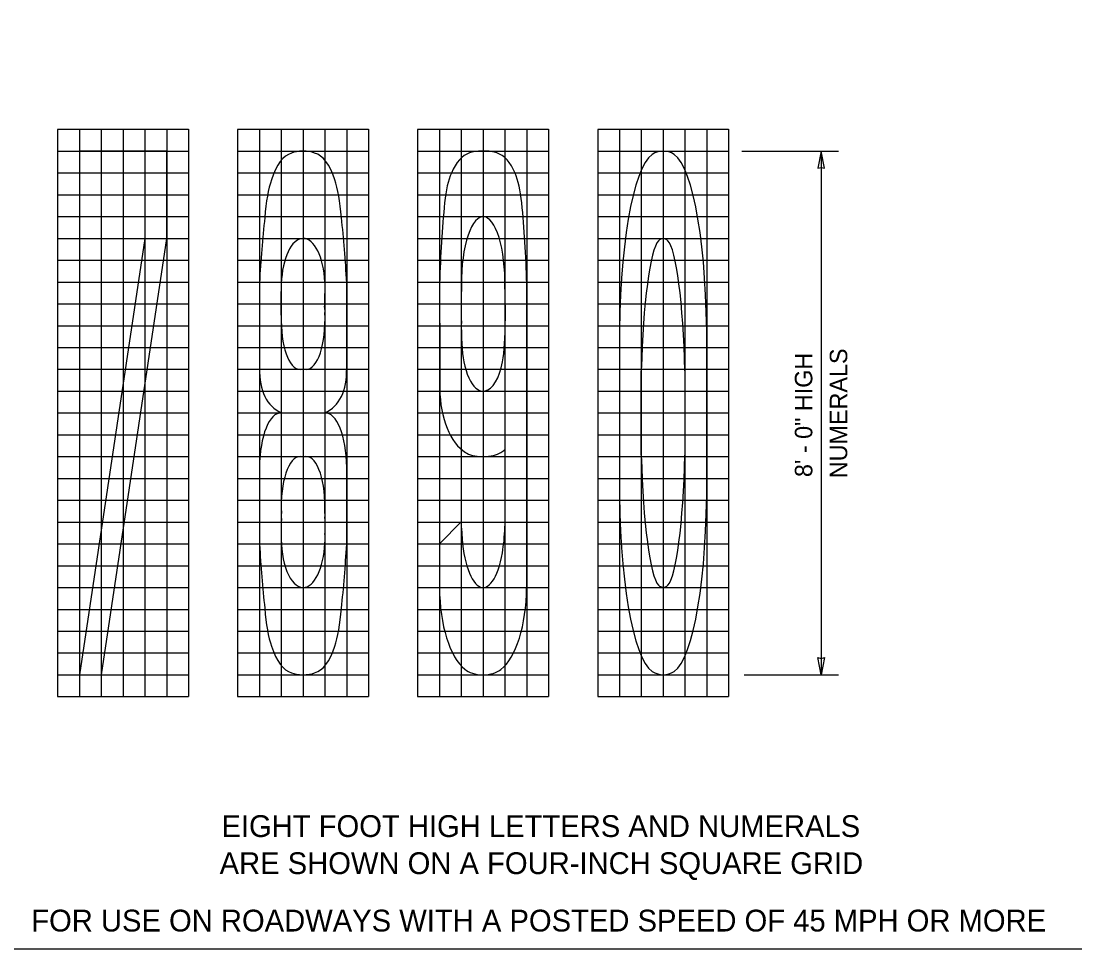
# Model space of a CAD drawing. Extents: x 99862 to 103151, y 100000 to 102076.
# Drawn here: x 100962 to 101927, y 100000 to 100850 of the extents above; entities that cross this region are included whole.
import ezdxf

# ---------------------------------------------------------------- set-up
doc = ezdxf.new("R2010")
doc.units = 0
for name, color, linetype in [('Level 1', 7, 'Continuous'), ('Level 15', 7, 'Continuous'), ('Level 20', 7, 'Continuous'), ('Level 4', 7, 'Continuous')]:
    doc.layers.add(name, color=color, linetype=linetype)

msp = doc.modelspace()

# ---------------------------------------------------------------- linework, layer by layer
at = {"layer": 'Level 1'}
msp.add_lwpolyline([(99862, 99999.5), (103151, 99999.5), (103151, 102075.5), (99862, 102075.5)], close=True, dxfattribs=at)
at = {"layer": 'Level 15'}
for p, q in [((101622.02, 100730.78), (101710.77, 100730.78)), ((101694.77, 100730.78), (101694.77, 100250.78)), ((101220.02, 100650.75), (101220.02, 100650.75)), ((101220.02, 100650.75), (101220.02, 100650.75)), ((101220.02, 100650.75), (101220.02, 100650.75)), ((101220.02, 100649.92), (101220.02, 100649.92)), ((101220.02, 100649.92), (101220.02, 100649.92)), ((101220.02, 100649.92), (101220.02, 100649.92)), ((101180.02, 100610.16), (101180.08, 100582.8)), ((101240.02, 100610.79), (101240.02, 100600.16)), ((101259.97, 100582.8), (101260.02, 100610.16)), ((101345.1, 100606.34), (101345.22, 100540.2)), ((101404.99, 100604.22), (101405.1, 100575.2)), ((101424.98, 100540.17), (101425.1, 100606.31)), ((101200.02, 100582.8), (101200.02, 100602.03)), ((101365.1, 100575.23), (101365.21, 100602.15)), ((101239.69, 100587.77), (101239.97, 100582.8)), ((101180.08, 100582.8), (101180.08, 100531.82)), ((101199.99, 100580.39), (101200.02, 100581.45)), ((101200.02, 100581.45), (101200.02, 100582.8)), ((101259.97, 100531.82), (101259.97, 100582.8)), ((101510.03, 100549.53), (101510.03, 100490.78)), ((101590.02, 100490.78), (101590.02, 100549.53)), ((101345.22, 100540.2), (101345.22, 100512.98)), ((101424.98, 100533.28), (101424.98, 100540.17)), ((101222.7, 100530.58), (101217.35, 100530.58)), ((101425.06, 100387.03), (101425.06, 100533.28)), ((101530.03, 100490.78), (101530.03, 100529.53)), ((101570.03, 100529.53), (101570.03, 100490.78)), ((101345.22, 100512.98), (101345.35, 100512.98)), ((101510.03, 100490.78), (101510.03, 100432.03)), ((101530.03, 100452.03), (101530.03, 100490.78)), ((101570.03, 100490.78), (101570.03, 100452.03)), ((101590.02, 100432.03), (101590.02, 100490.78)), ((101217.43, 100450.99), (101222.61, 100450.99)), ((101384.07, 100450.8), (101385.1, 100450.75)), ((101405.06, 100457.24), (101405.06, 100387.03)), ((101180.08, 100441.04), (101180.08, 100391.93)), ((101259.97, 100391.93), (101259.97, 100441.04)), ((101180.08, 100391.93), (101180.02, 100371.41)), ((101200.14, 100393.95), (101200.12, 100398.77)), ((101239.93, 100398.77), (101239.95, 100395.51)), ((101240.02, 100394), (101240.02, 100380.16)), ((101260.02, 100371.41), (101259.97, 100391.93)), ((101365.16, 100391.16), (101345.06, 100370.75)), ((101365.15, 100385.07), (101365.16, 100391.16)), ((101424.94, 100330.75), (101425.06, 100387.03)), ((101345.06, 100370.75), (101345.06, 100330.75)), ((101220.02, 100330.81), (101220.02, 100330.81)), ((101424.82, 100330.75), (101424.94, 100330.75)), ((101624.27, 100250.78), (101710.77, 100250.78))]:
    msp.add_line(p, q, dxfattribs=at)
for points in [[(101075.02, 100650.78), (101015.02, 100250.78), (101035.34, 100250.78), (101095.02, 100650.78), (101095.02, 100730.78), (101015.02, 100730.78), (101015.02, 100650.78)], [(101694.77, 100730.78), (101691.69, 100715.06), (101694.77, 100715.79), (101697.86, 100715.06)], [(101694.77, 100250.78), (101691.69, 100266.51), (101694.77, 100265.78), (101697.86, 100266.51)]]:
    msp.add_lwpolyline(points, close=True, dxfattribs=at)
for centre, major_axis, ratio, start_param, end_param in [((101261.8, 100487.41), (51.44, -241.79), 0.246365, 3.159715, 3.546722), ((101219.99, 100726.1), (13.44, 0), 0.348837, 0.665473, 2.491733), ((101178.25, 100487.41), (-51.44, -241.79), 0.246365, 2.736464, 3.126953), ((101426.65, 100540.75), (-53.45, 188.59), 0.306336, 0.009968, 0.370894), ((101383.25, 100727.1), (12.93, 0.07), 0.287037, 1.501345, 2.532225), ((101384.19, 100730.21), (2.08, 0.01), 0.287037, 1.115416, 1.600804), ((101386.96, 100727.07), (-12.93, 0.07), 0.287037, 3.75096, 4.857801), ((101343.55, 100540.72), (53.45, 188.59), 0.306336, 5.912291, 6.273217), ((101540.03, 100310.01), (-10.47, -420.77), 0.199299, 3.026472, 3.266466), ((101550.02, 100530.37), (5, -199.16), 0.199299, 3.270146, 4.611011), ((101550.05, 100530.47), (-4.96, -199.07), 0.199299, 1.671694, 3.012648), ((101373.25, 100636.62), (-7.81, 83.62), 0.278967, 0.459981, 0.951847), ((101396.95, 100636.59), (7.81, 83.62), 0.278967, 5.331339, 5.823204), ((101208.4, 100610.03), (7.56, -106.98), 0.218823, 3.612153, 4.104018), ((101231.65, 100610.03), (-7.56, -106.98), 0.218823, 2.179168, 2.671033), ((101450.25, 100500.57), (-24.2, 367.41), 0.279414, 1.031763, 1.251037), ((101319.96, 100500.54), (24.2, 367.41), 0.279414, 5.032148, 5.251423), ((101385.06, 100609.53), (0, 61.25), 0.326531, 0.046211, 1.691605), ((101385.06, 100609.53), (0, 61.25), 0.326531, 0.017819, 0.046211), ((101385.06, 100609.53), (0, 61.25), 0.326531, 6.281207, 6.301005), ((101385.06, 100609.53), (0, 61.25), 0.326531, 4.6597, 6.281207), ((101252.64, 100500.55), (6.24, -341.1), 0.218821, 4.189125, 4.381242), ((101187.41, 100500.55), (-6.24, -341.1), 0.218821, 1.901943, 2.09406), ((101542.07, 100303.32), (-8.13, -347.15), 0.12203, 3.042542, 3.248083), ((101219.64, 100606.42), (-0.4, -44.36), 0.443662, 3.159722, 4.650111), ((101220, 100595.16), (0, -55.63), 0.353933, 3.140679, 3.157785), ((101220.13, 100605.63), (0.09, -45.16), 0.443662, 1.684508, 3.142616), ((101544.71, 100529.2), (-2.82, -120.33), 0.12203, 3.268534, 4.712481), ((101555.34, 100529.2), (2.82, -120.33), 0.12203, 1.570704, 3.018848), ((101219.64, 100606.42), (-0.4, -44.36), 0.443662, 4.650111, 4.815474), ((101450.25, 100500.57), (-24.2, 367.41), 0.279414, 1.251037, 1.260446), ((101385.06, 100609.53), (0, 61.25), 0.326531, 4.625574, 4.6597), ((101319.96, 100500.54), (24.2, 367.41), 0.279414, 5.022739, 5.032148), ((101219.84, 100594.69), (-1.44, -56.9), 0.353933, 1.457775, 1.608151), ((101219.84, 100594.69), (-1.44, -56.9), 0.353933, 1.608151, 1.675965), ((101219.89, 100583.11), (-2.82, -52.52), 0.375885, 4.784318, 6.297572), ((101220.16, 100583.11), (2.82, -52.52), 0.375885, 6.268799, 7.827952), ((101371.54, 100568.89), (0, 39.94), 0.163363, 1.411316, 2.46776), ((101398.62, 100568.88), (0, 40.16), 0.163363, 3.821205, 4.870391), ((101385.06, 100554.53), (0, 43.75), 0.435714, 1.966446, 2.78592), ((101383.09, 100559.94), (-2.26, 49.18), 0.428571, 3.209496, 4.222129), ((101327.39, 100654.33), (-134.22, -159.14), 0.381725, 5.846217, 6.385455), ((101112.65, 100654.33), (134.22, -159.14), 0.381725, 6.180916, 6.720154), ((101378.95, 100513.49), (-0.08, 61.71), 0.544507, 1.578427, 2.834124), ((101385.06, 100554.53), (0, 43.75), 0.435714, 2.78592, 3.084732), ((101385.06, 100554.53), (0, 43.75), 0.435714, 3.084732, 3.124945), ((101385.06, 100554.53), (0, 43.75), 0.435714, 3.124945, 3.145709), ((101384.9, 100569.3), (0, 58.52), 0.435714, 3.151101, 3.215129), ((101199.77, 100439.43), (0.37, -51.38), 0.383378, 3.107477, 4.678273), ((101240.27, 100439.43), (-0.37, -51.38), 0.383378, 1.604912, 3.175708), ((101219.93, 100398.46), (2.82, -52.52), 0.375885, 3.124969, 4.686367), ((101220.12, 100398.46), (-2.82, -52.52), 0.375885, 1.596818, 3.158216), ((101385.09, 100458.46), (-18.74, 0.05), 0.409437, 0.523878, 1.517526), ((101385.12, 100458.43), (18.74, 0.05), 0.409437, 4.710429, 5.759307), ((101391.26, 100513.46), (0.08, 61.71), 0.544507, 3.449061, 3.567317), ((101544.71, 100452.37), (2.82, -120.33), 0.12203, 4.712297, 6.156244), ((101555.34, 100452.37), (-2.82, -120.33), 0.12203, 0.122745, 1.570889), ((101550.02, 100451.2), (-5, -199.16), 0.199299, 4.813767, 6.154632), ((101550.05, 100451.1), (4.96, -199.07), 0.199299, 0.128945, 1.469898), ((101220.04, 100386.25), (-0.34, -56.86), 0.353933, 4.597839, 4.832837), ((101220.04, 100386.25), (-0.34, -56.86), 0.353933, 4.58824, 4.597839), ((101220.04, 100386.25), (-0.34, -56.86), 0.353933, 4.578654, 4.58824), ((101220.04, 100386.25), (-0.34, -56.86), 0.353933, 1.709628, 1.736462), ((101385.06, 100390.75), (0, 60), 0.333333, 1.665564, 4.222129), ((101235.54, 100390), (21.92, 192.2), 0.875536, 4.669008, 4.790083), ((101235.54, 100390), (21.92, 192.2), 0.875536, 4.790083, 4.796543), ((101251.89, 100479.28), (-6.09, -337.57), 0.218821, 5.041601, 5.044505), ((101219.64, 100375.14), (0.39, -44.35), 0.443662, 4.609304, 6.265056), ((101220.5, 100374.98), (-0.48, -44.2), 0.443662, 6.282162, 7.780625), ((101220.5, 100374.98), (-0.48, -44.2), 0.443662, 1.497439, 1.693033), ((101188.15, 100479.28), (6.09, -337.57), 0.218821, 1.23868, 1.241584), ((101251.89, 100479.28), (-6.09, -337.57), 0.218821, 5.044505, 5.235652), ((101188.15, 100479.28), (6.09, -337.57), 0.218821, 1.047533, 1.23868), ((101542.07, 100678.25), (8.13, -347.15), 0.12203, 6.176695, 6.382236), ((101219.99, 100386.41), (0, -55.63), 0.353933, 6.266993, 6.284099), ((101378.81, 100331.3), (0, 79.3), 0.425602, 1.577801, 2.825639), ((101391.22, 100331.41), (0.07, 79.34), 0.423506, 3.448728, 4.704426), ((101208.4, 100371.54), (-7.56, -106.98), 0.218823, 5.32076, 5.812625), ((101231.65, 100371.54), (7.56, -106.98), 0.218823, 0.47056, 0.962425), ((101261.8, 100494.16), (-51.44, -241.79), 0.246365, 5.878056, 6.265063), ((101178.25, 100494.16), (51.44, -241.79), 0.246365, 0.014639, 0.405129), ((101384.9, 100260.76), (18.95, 0), 0.52642, 3.647253, 5.759318), ((101219.99, 100255.47), (13.44, 0), 0.348837, 3.791452, 5.617712), ((101540.03, 100671.56), (10.47, -420.77), 0.199299, 6.158312, 6.398306)]:
    msp.add_ellipse(centre, major_axis=major_axis, ratio=ratio, start_param=start_param, end_param=end_param, dxfattribs=at)
at = {"layer": 'Level 4'}
for p, q in [((100995.02, 100750.78), (101115.02, 100750.78)), ((100995.02, 100750.77), (100995.02, 100230.8)), ((101015.02, 100750.78), (101015.02, 100230.78)), ((101035.02, 100750.78), (101035.02, 100230.78)), ((101055.02, 100750.78), (101055.02, 100230.78)), ((101075.02, 100750.78), (101075.02, 100230.78)), ((101095.02, 100750.78), (101095.02, 100230.78)), ((101115.02, 100750.78), (101115.02, 100230.78)), ((101160.02, 100750.78), (101280.02, 100750.78)), ((101160.02, 100750.77), (101160.02, 100230.8)), ((101180.02, 100750.78), (101180.02, 100230.78)), ((101200.02, 100750.78), (101200.02, 100230.78)), ((101220.02, 100750.78), (101220.02, 100230.78)), ((101240.02, 100750.78), (101240.02, 100230.78)), ((101260.02, 100750.78), (101260.02, 100230.78)), ((101280.02, 100750.78), (101280.02, 100230.78)), ((101325.02, 100750.78), (101445.02, 100750.78)), ((101325.02, 100750.77), (101325.02, 100230.8)), ((101345.02, 100750.78), (101345.02, 100230.78)), ((101365.02, 100750.78), (101365.02, 100230.78)), ((101385.02, 100750.78), (101385.02, 100230.78)), ((101405.02, 100750.78), (101405.02, 100230.78)), ((101425.02, 100750.78), (101425.02, 100230.78)), ((101445.02, 100750.78), (101445.02, 100230.78)), ((101490.02, 100750.78), (101610.02, 100750.78)), ((101490.02, 100750.77), (101490.02, 100230.8)), ((101510.02, 100750.78), (101510.02, 100230.78)), ((101530.02, 100750.78), (101530.02, 100230.78)), ((101550.02, 100750.78), (101550.02, 100230.78)), ((101570.02, 100750.78), (101570.02, 100230.78)), ((101590.02, 100750.78), (101590.02, 100230.78)), ((101610.02, 100750.78), (101610.02, 100230.78)), ((100995.02, 100730.78), (101115.02, 100730.78)), ((101160.02, 100730.78), (101280.02, 100730.78)), ((101325.02, 100730.78), (101445.02, 100730.78)), ((101490.02, 100730.78), (101610.02, 100730.78)), ((100995.02, 100710.78), (101115.02, 100710.78)), ((101160.02, 100710.78), (101280.02, 100710.78)), ((101325.02, 100710.78), (101445.02, 100710.78)), ((101490.02, 100710.78), (101610.02, 100710.78)), ((100995.02, 100690.78), (101115.02, 100690.78)), ((101160.02, 100690.78), (101280.02, 100690.78)), ((101325.02, 100690.78), (101445.02, 100690.78)), ((101490.02, 100690.78), (101610.02, 100690.78)), ((100995.02, 100670.78), (101115.02, 100670.78)), ((101160.02, 100670.78), (101280.02, 100670.78)), ((101325.02, 100670.78), (101445.02, 100670.78)), ((101490.02, 100670.78), (101610.02, 100670.78)), ((100995.02, 100650.78), (101115.02, 100650.78)), ((101160.02, 100650.78), (101280.02, 100650.78)), ((101325.02, 100650.78), (101445.02, 100650.78)), ((101490.02, 100650.78), (101610.02, 100650.78)), ((100995.02, 100630.78), (101115.02, 100630.78)), ((101160.02, 100630.78), (101280.02, 100630.78)), ((101325.02, 100630.78), (101445.02, 100630.78)), ((101490.02, 100630.78), (101610.02, 100630.78)), ((100995.02, 100610.78), (101115.02, 100610.78)), ((101160.02, 100610.78), (101280.02, 100610.78)), ((101325.02, 100610.78), (101445.02, 100610.78)), ((101490.02, 100610.78), (101610.02, 100610.78)), ((100995.02, 100590.78), (101115.02, 100590.78)), ((101160.02, 100590.78), (101280.02, 100590.78)), ((101325.02, 100590.78), (101445.02, 100590.78)), ((101490.02, 100590.78), (101610.02, 100590.78)), ((100995.02, 100570.78), (101115.02, 100570.78)), ((101160.02, 100570.78), (101280.02, 100570.78)), ((101325.02, 100570.78), (101445.02, 100570.78)), ((101490.02, 100570.78), (101610.02, 100570.78)), ((100995.02, 100550.78), (101115.02, 100550.78)), ((101160.02, 100550.78), (101280.02, 100550.78)), ((101325.02, 100550.78), (101445.02, 100550.78)), ((101490.02, 100550.78), (101610.02, 100550.78)), ((100995.02, 100530.78), (101115.02, 100530.78)), ((101160.02, 100530.78), (101280.02, 100530.78)), ((101325.02, 100530.78), (101445.02, 100530.78)), ((101490.02, 100530.78), (101610.02, 100530.78)), ((100995.02, 100510.78), (101115.02, 100510.78)), ((101160.02, 100510.78), (101280.02, 100510.78)), ((101325.02, 100510.78), (101445.02, 100510.78)), ((101490.02, 100510.78), (101610.02, 100510.78)), ((100995.02, 100490.78), (101115.02, 100490.78)), ((101160.02, 100490.78), (101280.02, 100490.78)), ((101325.02, 100490.78), (101445.02, 100490.78)), ((101490.02, 100490.78), (101610.02, 100490.78)), ((100995.02, 100470.78), (101115.02, 100470.78)), ((101160.02, 100470.78), (101280.02, 100470.78)), ((101325.02, 100470.78), (101445.02, 100470.78)), ((101490.02, 100470.78), (101610.02, 100470.78)), ((100995.02, 100450.78), (101115.02, 100450.78)), ((101160.02, 100450.78), (101280.02, 100450.78)), ((101325.02, 100450.78), (101445.02, 100450.78)), ((101490.02, 100450.78), (101610.02, 100450.78)), ((100995.02, 100430.78), (101115.02, 100430.78)), ((101160.02, 100430.78), (101280.02, 100430.78)), ((101325.02, 100430.78), (101445.02, 100430.78)), ((101490.02, 100430.78), (101610.02, 100430.78)), ((100995.02, 100410.78), (101115.02, 100410.78)), ((101160.02, 100410.78), (101280.02, 100410.78)), ((101325.02, 100410.78), (101445.02, 100410.78)), ((101490.02, 100410.78), (101610.02, 100410.78)), ((100995.02, 100390.78), (101115.02, 100390.78)), ((101160.02, 100390.78), (101280.02, 100390.78)), ((101325.02, 100390.78), (101445.02, 100390.78)), ((101490.02, 100390.78), (101610.02, 100390.78)), ((100995.02, 100370.78), (101115.02, 100370.78)), ((101160.02, 100370.78), (101280.02, 100370.78)), ((101325.02, 100370.78), (101445.02, 100370.78)), ((101490.02, 100370.78), (101610.02, 100370.78)), ((100995.02, 100350.78), (101115.02, 100350.78)), ((101160.02, 100350.78), (101280.02, 100350.78)), ((101325.02, 100350.78), (101445.02, 100350.78)), ((101490.02, 100350.78), (101610.02, 100350.78)), ((100995.02, 100330.78), (101115.02, 100330.78)), ((101160.02, 100330.78), (101280.02, 100330.78)), ((101325.02, 100330.78), (101445.02, 100330.78)), ((101490.02, 100330.78), (101610.02, 100330.78)), ((100995.02, 100310.78), (101115.02, 100310.78)), ((101160.02, 100310.78), (101280.02, 100310.78)), ((101325.02, 100310.78), (101445.02, 100310.78)), ((101490.02, 100310.78), (101610.02, 100310.78)), ((100995.02, 100290.78), (101115.02, 100290.78)), ((101160.02, 100290.78), (101280.02, 100290.78)), ((101325.02, 100290.78), (101445.02, 100290.78)), ((101490.02, 100290.78), (101610.02, 100290.78)), ((100995.02, 100270.78), (101115.02, 100270.78)), ((101160.02, 100270.78), (101280.02, 100270.78)), ((101325.02, 100270.78), (101445.02, 100270.78)), ((101490.02, 100270.78), (101610.02, 100270.78)), ((100995.02, 100250.78), (101115.02, 100250.78)), ((101160.02, 100250.78), (101280.02, 100250.78)), ((101325.02, 100250.78), (101445.02, 100250.78)), ((101490.02, 100250.78), (101610.02, 100250.78)), ((100995.02, 100230.78), (101115.02, 100230.78)), ((101160.02, 100230.78), (101280.02, 100230.78)), ((101325.02, 100230.78), (101445.02, 100230.78)), ((101490.02, 100230.78), (101610.02, 100230.78))]:
    msp.add_line(p, q, dxfattribs=at)

# ---------------------------------------------------------------- texts
at = {"layer": 'Level 20'}
for s, p in [('NUMERALS', (101718.77, 100431.01)), ('8\' - 0" HIGH', (101686.77, 100432.03))]:
    msp.add_text(s, height=16, rotation=90, dxfattribs=at).set_placement(p)
for s, p in [('EIGHT FOOT HIGH LETTERS AND NUMERALS ', (101145.18, 100102.09)), ('ARE SHOWN ON A FOUR-INCH SQUARE GRID', (101143.48, 100068.09)), ('FOR USE ON ROADWAYS WITH A POSTED SPEED OF 45 MPH OR MORE', (100970.82, 100015.47))]:
    msp.add_text(s, height=20, dxfattribs=at).set_placement(p)

doc.saveas('drawing.dxf')
